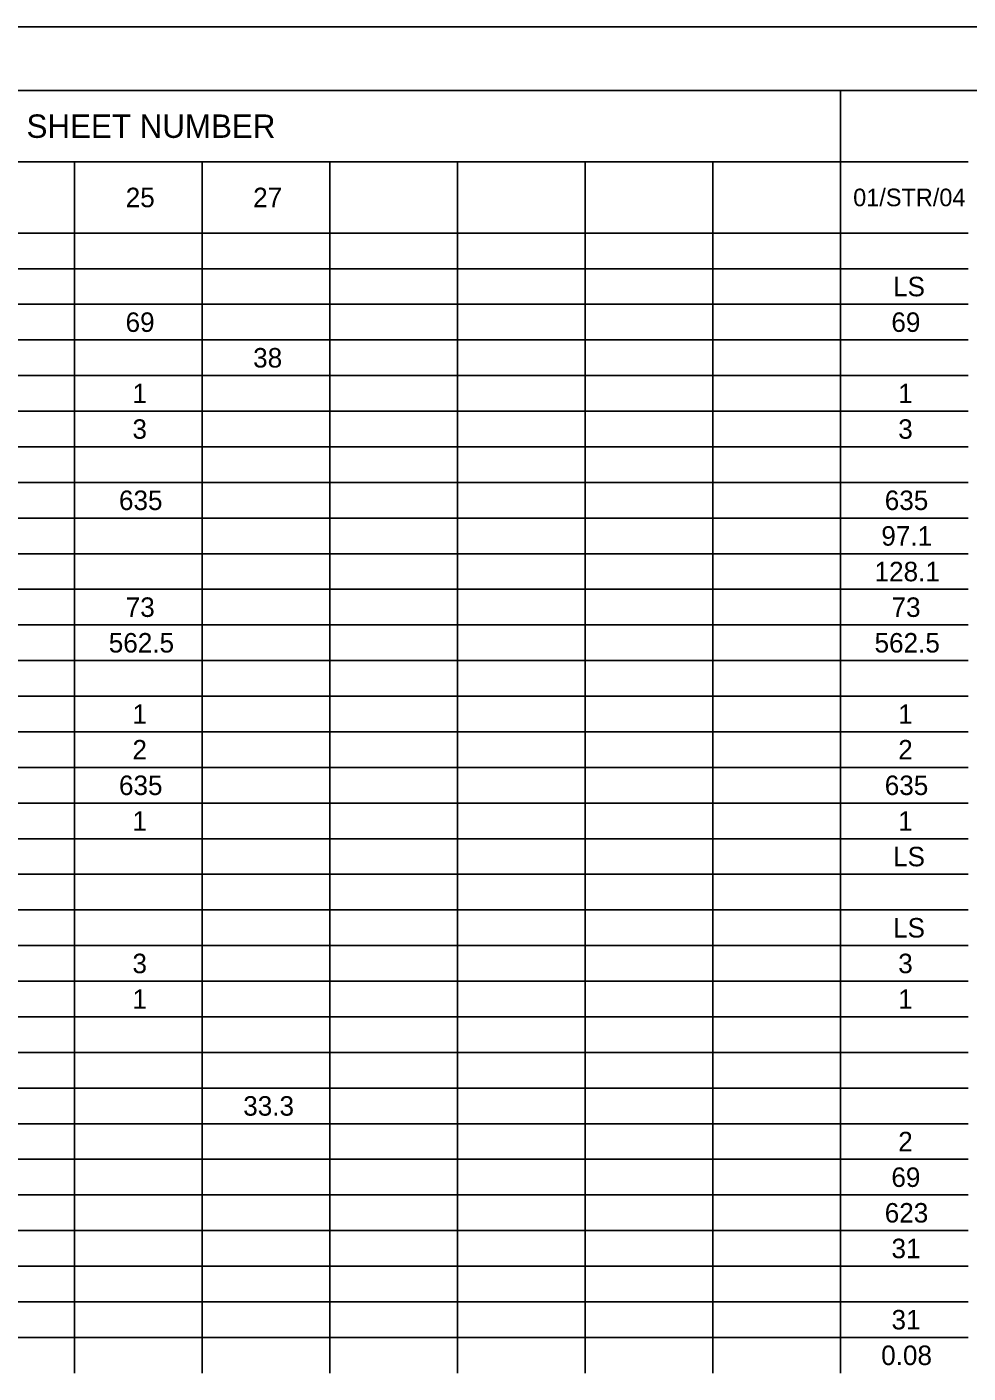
# Model space of a CAD drawing. Extents: x 0 to 34, y 0 to 22.
# Drawn here: x 6.14 to 13.53, y 11.42 to 22 of the extents above; entities that cross this region are included whole.
import ezdxf

# ---------------------------------------------------------------- set-up
doc = ezdxf.new("R2010")
doc.units = 0
for name, color, linetype in [('Default', 7, 'Continuous'), ('SH_Border', 7, 'Continuous'), ('SH_Cut_Line', 7, 'Continuous')]:
    doc.layers.add(name, color=color, linetype=linetype)

msp = doc.modelspace()

# ---------------------------------------------------------------- linework, layer by layer
at = {"layer": 'Default'}
for p, q in [((1.5, 21.5), (6.513, 21.5)), ((6.513, 21.5), (7.515, 21.5)), ((7.515, 21.5), (12.528, 21.5)), ((12.528, 21.5), (13.53, 21.5)), ((12.528, 21.5), (12.528, 21.22)), ((12.528, 21.22), (12.528, 20.94)), ((1.5, 20.94), (6.513, 20.94)), ((6.513, 20.94), (7.515, 20.94)), ((6.513, 20.94), (6.513, 20.66)), ((7.515, 20.94), (12.528, 20.94)), ((7.515, 20.94), (7.515, 20.66)), ((8.518, 20.94), (8.518, 20.66)), ((9.52, 20.94), (9.52, 20.66)), ((10.523, 20.94), (10.523, 20.66)), ((11.525, 20.94), (11.525, 20.66)), ((12.528, 20.94), (13.53, 20.94)), ((12.528, 20.94), (12.528, 20.66)), ((6.513, 20.66), (6.513, 20.38)), ((7.515, 20.66), (7.515, 20.38)), ((8.518, 20.66), (8.518, 20.38)), ((9.52, 20.66), (9.52, 20.38)), ((10.523, 20.66), (10.523, 20.38)), ((11.525, 20.66), (11.525, 20.38)), ((12.528, 20.66), (12.528, 20.38)), ((1.5, 20.38), (6.513, 20.38)), ((6.513, 20.38), (7.515, 20.38)), ((6.513, 20.38), (6.513, 20.1)), ((7.515, 20.38), (12.528, 20.38)), ((7.515, 20.38), (7.515, 20.1)), ((8.518, 20.38), (8.518, 20.1)), ((9.52, 20.38), (9.52, 20.1)), ((10.523, 20.38), (10.523, 20.1)), ((11.525, 20.38), (11.525, 20.1)), ((12.528, 20.38), (13.53, 20.38)), ((12.528, 20.38), (12.528, 20.1)), ((1.5, 20.1), (6.513, 20.1)), ((6.513, 20.1), (7.515, 20.1)), ((6.513, 20.1), (6.513, 18.7)), ((7.515, 20.1), (12.528, 20.1)), ((7.515, 20.1), (7.515, 18.7)), ((8.518, 20.1), (8.518, 18.7)), ((9.52, 20.1), (9.52, 18.7)), ((10.523, 20.1), (10.523, 18.7)), ((11.525, 20.1), (11.525, 18.7)), ((12.528, 20.1), (13.53, 20.1)), ((12.528, 20.1), (12.528, 18.7)), ((1.5, 19.82), (6.513, 19.82)), ((6.513, 19.82), (7.515, 19.82)), ((7.515, 19.82), (12.528, 19.82)), ((12.528, 19.82), (13.53, 19.82)), ((1.5, 19.54), (6.513, 19.54)), ((6.513, 19.54), (7.515, 19.54)), ((7.515, 19.54), (12.528, 19.54)), ((12.528, 19.54), (13.53, 19.54)), ((1.5, 19.26), (6.513, 19.26)), ((6.513, 19.26), (7.515, 19.26)), ((7.515, 19.26), (12.528, 19.26)), ((12.528, 19.26), (13.53, 19.26)), ((1.5, 18.98), (6.513, 18.98)), ((6.513, 18.98), (7.515, 18.98)), ((7.515, 18.98), (12.528, 18.98)), ((12.528, 18.98), (13.53, 18.98)), ((1.5, 18.7), (6.513, 18.7)), ((6.513, 18.7), (7.515, 18.7)), ((6.513, 18.7), (6.513, 18.14)), ((7.515, 18.7), (12.528, 18.7)), ((7.515, 18.7), (7.515, 18.14)), ((8.518, 18.7), (8.518, 18.14)), ((9.52, 18.7), (9.52, 18.14)), ((10.523, 18.7), (10.523, 18.14)), ((11.525, 18.7), (11.525, 18.14)), ((12.528, 18.7), (13.53, 18.7)), ((12.528, 18.7), (12.528, 18.14)), ((1.5, 18.42), (6.513, 18.42)), ((6.513, 18.42), (7.515, 18.42)), ((7.515, 18.42), (12.528, 18.42)), ((12.528, 18.42), (13.53, 18.42)), ((1.5, 18.14), (6.513, 18.14)), ((6.513, 18.14), (7.515, 18.14)), ((6.513, 18.14), (6.513, 17.86)), ((7.515, 18.14), (12.528, 18.14)), ((7.515, 18.14), (7.515, 17.86)), ((8.518, 18.14), (8.518, 17.86)), ((9.52, 18.14), (9.52, 17.86)), ((10.523, 18.14), (10.523, 17.86)), ((11.525, 18.14), (11.525, 17.86)), ((12.528, 18.14), (13.53, 18.14)), ((12.528, 18.14), (12.528, 17.86)), ((1.5, 17.86), (6.513, 17.86)), ((6.513, 17.86), (7.515, 17.86)), ((6.513, 17.86), (6.513, 17.58)), ((7.515, 17.86), (12.528, 17.86)), ((7.515, 17.86), (7.515, 17.58)), ((8.518, 17.86), (8.518, 17.58)), ((9.52, 17.86), (9.52, 17.58)), ((10.523, 17.86), (10.523, 17.58)), ((11.525, 17.86), (11.525, 17.58)), ((12.528, 17.86), (13.53, 17.86)), ((12.528, 17.86), (12.528, 17.58)), ((1.5, 17.58), (6.513, 17.58)), ((6.513, 17.58), (7.515, 17.58)), ((6.513, 17.58), (6.513, 17.3)), ((7.515, 17.58), (12.528, 17.58)), ((7.515, 17.58), (7.515, 17.3)), ((8.518, 17.58), (8.518, 17.3)), ((9.52, 17.58), (9.52, 17.3)), ((10.523, 17.58), (10.523, 17.3)), ((11.525, 17.58), (11.525, 17.3)), ((12.528, 17.58), (13.53, 17.58)), ((12.528, 17.58), (12.528, 17.3)), ((1.5, 17.3), (6.513, 17.3)), ((6.513, 17.3), (7.515, 17.3)), ((6.513, 17.3), (6.513, 17.02)), ((7.515, 17.3), (12.528, 17.3)), ((7.515, 17.3), (7.515, 17.02)), ((8.518, 17.3), (8.518, 17.02)), ((9.52, 17.3), (9.52, 17.02)), ((10.523, 17.3), (10.523, 17.02)), ((11.525, 17.3), (11.525, 17.02)), ((12.528, 17.3), (13.53, 17.3)), ((12.528, 17.3), (12.528, 17.02)), ((1.5, 17.02), (6.513, 17.02)), ((6.513, 17.02), (7.515, 17.02)), ((6.513, 17.02), (6.513, 16.74)), ((7.515, 17.02), (12.528, 17.02)), ((7.515, 17.02), (7.515, 16.74)), ((8.518, 17.02), (8.518, 16.74)), ((9.52, 17.02), (9.52, 16.74)), ((10.523, 17.02), (10.523, 16.74)), ((11.525, 17.02), (11.525, 16.74)), ((12.528, 17.02), (13.53, 17.02)), ((12.528, 17.02), (12.528, 16.74)), ((1.5, 16.74), (6.513, 16.74)), ((6.513, 16.74), (7.515, 16.74)), ((6.513, 16.74), (6.513, 16.18)), ((7.515, 16.74), (12.528, 16.74)), ((7.515, 16.74), (7.515, 16.18)), ((8.518, 16.74), (8.518, 16.18)), ((9.52, 16.74), (9.52, 16.18)), ((10.523, 16.74), (10.523, 16.18)), ((11.525, 16.74), (11.525, 16.18)), ((12.528, 16.74), (13.53, 16.74)), ((12.528, 16.74), (12.528, 16.18)), ((1.5, 16.46), (6.513, 16.46)), ((6.513, 16.46), (7.515, 16.46)), ((7.515, 16.46), (12.528, 16.46)), ((12.528, 16.46), (13.53, 16.46)), ((1.5, 16.18), (6.513, 16.18)), ((6.513, 16.18), (7.515, 16.18)), ((6.513, 16.18), (6.513, 15.9)), ((7.515, 16.18), (12.528, 16.18)), ((7.515, 16.18), (7.515, 15.9)), ((8.518, 16.18), (8.518, 15.9)), ((9.52, 16.18), (9.52, 15.9)), ((10.523, 16.18), (10.523, 15.9)), ((11.525, 16.18), (11.525, 15.9)), ((12.528, 16.18), (13.53, 16.18)), ((12.528, 16.18), (12.528, 15.9)), ((1.5, 15.9), (6.513, 15.9)), ((6.513, 15.9), (7.515, 15.9)), ((6.513, 15.9), (6.513, 15.62)), ((7.515, 15.9), (12.528, 15.9)), ((7.515, 15.9), (7.515, 15.62)), ((8.518, 15.9), (8.518, 15.62)), ((9.52, 15.9), (9.52, 15.62)), ((10.523, 15.9), (10.523, 15.62)), ((11.525, 15.9), (11.525, 15.62)), ((12.528, 15.9), (13.53, 15.9)), ((12.528, 15.9), (12.528, 15.62)), ((1.5, 15.62), (6.513, 15.62)), ((6.513, 15.62), (7.515, 15.62)), ((6.513, 15.62), (6.513, 15.34)), ((7.515, 15.62), (12.528, 15.62)), ((7.515, 15.62), (7.515, 15.34)), ((8.518, 15.62), (8.518, 15.34)), ((9.52, 15.62), (9.52, 15.34)), ((10.523, 15.62), (10.523, 15.34)), ((11.525, 15.62), (11.525, 15.34)), ((12.528, 15.62), (13.53, 15.62)), ((12.528, 15.62), (12.528, 15.34)), ((1.5, 15.34), (6.513, 15.34)), ((6.513, 15.34), (7.515, 15.34)), ((6.513, 15.34), (6.513, 14.78)), ((7.515, 15.34), (12.528, 15.34)), ((7.515, 15.34), (7.515, 14.78)), ((8.518, 15.34), (8.518, 14.78)), ((9.52, 15.34), (9.52, 14.78)), ((10.523, 15.34), (10.523, 14.78)), ((11.525, 15.34), (11.525, 14.78)), ((12.528, 15.34), (13.53, 15.34)), ((12.528, 15.34), (12.528, 14.78)), ((1.5, 15.06), (6.513, 15.06)), ((6.513, 15.06), (7.515, 15.06)), ((7.515, 15.06), (12.528, 15.06)), ((12.528, 15.06), (13.53, 15.06)), ((1.5, 14.78), (6.513, 14.78)), ((6.513, 14.78), (7.515, 14.78)), ((6.513, 14.78), (6.513, 14.5)), ((7.515, 14.78), (12.528, 14.78)), ((7.515, 14.78), (7.515, 14.5)), ((8.518, 14.78), (8.518, 14.5)), ((9.52, 14.78), (9.52, 14.5)), ((10.523, 14.78), (10.523, 14.5)), ((11.525, 14.78), (11.525, 14.5)), ((12.528, 14.78), (13.53, 14.78)), ((12.528, 14.78), (12.528, 14.5)), ((1.5, 14.5), (6.513, 14.5)), ((6.513, 14.5), (7.515, 14.5)), ((6.513, 14.5), (6.513, 14.22)), ((7.515, 14.5), (12.528, 14.5)), ((7.515, 14.5), (7.515, 14.22)), ((8.518, 14.5), (8.518, 14.22)), ((9.52, 14.5), (9.52, 14.22)), ((10.523, 14.5), (10.523, 14.22)), ((11.525, 14.5), (11.525, 14.22)), ((12.528, 14.5), (13.53, 14.5)), ((12.528, 14.5), (12.528, 14.22)), ((1.5, 14.22), (6.513, 14.22)), ((6.513, 14.22), (7.515, 14.22)), ((6.513, 14.22), (6.513, 13.94)), ((7.515, 14.22), (12.528, 14.22)), ((7.515, 14.22), (7.515, 13.94)), ((8.518, 14.22), (8.518, 13.94)), ((9.52, 14.22), (9.52, 13.94)), ((10.523, 14.22), (10.523, 13.94)), ((11.525, 14.22), (11.525, 13.94)), ((12.528, 14.22), (13.53, 14.22)), ((12.528, 14.22), (12.528, 13.94)), ((1.5, 13.94), (6.513, 13.94)), ((6.513, 13.94), (7.515, 13.94)), ((6.513, 13.94), (6.513, 11.7)), ((7.515, 13.94), (12.528, 13.94)), ((7.515, 13.94), (7.515, 11.7)), ((8.518, 13.94), (8.518, 11.7)), ((9.52, 13.94), (9.52, 11.7)), ((10.523, 13.94), (10.523, 11.7)), ((11.525, 13.94), (11.525, 11.7)), ((12.528, 13.94), (13.53, 13.94)), ((12.528, 13.94), (12.528, 11.7)), ((1.5, 13.66), (6.513, 13.66)), ((6.513, 13.66), (7.515, 13.66)), ((7.515, 13.66), (12.528, 13.66)), ((12.528, 13.66), (13.53, 13.66)), ((1.5, 13.38), (6.513, 13.38)), ((6.513, 13.38), (7.515, 13.38)), ((7.515, 13.38), (12.528, 13.38)), ((12.528, 13.38), (13.53, 13.38)), ((1.5, 13.1), (6.513, 13.1)), ((6.513, 13.1), (7.515, 13.1)), ((7.515, 13.1), (12.528, 13.1)), ((12.528, 13.1), (13.53, 13.1)), ((1.5, 12.82), (6.513, 12.82)), ((6.513, 12.82), (7.515, 12.82)), ((7.515, 12.82), (12.528, 12.82)), ((12.528, 12.82), (13.53, 12.82)), ((1.5, 12.54), (6.513, 12.54)), ((6.513, 12.54), (7.515, 12.54)), ((7.515, 12.54), (12.528, 12.54)), ((12.528, 12.54), (13.53, 12.54)), ((1.5, 12.26), (6.513, 12.26)), ((6.513, 12.26), (7.515, 12.26)), ((7.515, 12.26), (12.528, 12.26)), ((12.528, 12.26), (13.53, 12.26)), ((1.5, 11.98), (6.513, 11.98)), ((6.513, 11.98), (7.515, 11.98)), ((7.515, 11.98), (12.528, 11.98)), ((12.528, 11.98), (13.53, 11.98)), ((1.5, 11.7), (6.513, 11.7)), ((6.513, 11.7), (7.515, 11.7)), ((6.513, 11.7), (6.513, 11.42)), ((7.515, 11.7), (12.528, 11.7)), ((7.515, 11.7), (7.515, 11.42)), ((8.518, 11.7), (8.518, 11.42)), ((9.52, 11.7), (9.52, 11.42)), ((10.523, 11.7), (10.523, 11.42)), ((11.525, 11.7), (11.525, 11.42)), ((12.528, 11.7), (13.53, 11.7)), ((12.528, 11.7), (12.528, 11.42))]:
    msp.add_line(p, q, dxfattribs=at)
at = {"layer": 'SH_Border'}
msp.add_lwpolyline([(1.5, 21.5), (33.5, 21.5), (33.5, 0.5), (1.5, 0.5)], close=True, dxfattribs=at)
at = {"layer": 'SH_Cut_Line'}
msp.add_lwpolyline([(0, 0), (34, 0), (34, 22), (0, 22)], close=True, dxfattribs=at)

# ---------------------------------------------------------------- texts
at = {"layer": 'Default'}
for s, height, p in [('SHEET NUMBER', 0.184, (6.135, 21.128)), ('25', 0.1533, (6.914, 20.583)), ('27', 0.1533, (7.915, 20.583)), ('01/STR/04', 0.138, (12.628, 20.591)), ('LS', 0.1533, (12.941, 19.883)), ('69', 0.1533, (6.913, 19.603)), ('69', 0.1533, (12.928, 19.603)), ('38', 0.1533, (7.915, 19.323)), ('1', 0.153, (6.967, 19.043)), ('1', 0.153, (12.982, 19.043)), ('3', 0.153, (6.967, 18.763)), ('3', 0.153, (12.982, 18.763)), ('635', 0.1533, (6.861, 18.203)), ('635', 0.1533, (12.876, 18.203)), ('97.1', 0.1533, (12.849, 17.923)), ('128.1', 0.1533, (12.796, 17.643)), ('73', 0.1533, (6.914, 17.363)), ('73', 0.1533, (12.929, 17.363)), ('562.5', 0.1533, (6.781, 17.083)), ('562.5', 0.1533, (12.796, 17.083)), ('1', 0.153, (6.967, 16.523)), ('1', 0.153, (12.982, 16.523)), ('2', 0.153, (6.967, 16.243)), ('2', 0.153, (12.982, 16.243)), ('635', 0.1533, (6.861, 15.963)), ('635', 0.1533, (12.876, 15.963)), ('1', 0.153, (6.967, 15.683)), ('1', 0.153, (12.982, 15.683)), ('LS', 0.1533, (12.941, 15.403)), ('LS', 0.1533, (12.941, 14.843)), ('3', 0.153, (6.967, 14.563)), ('3', 0.153, (12.982, 14.563)), ('1', 0.153, (6.967, 14.283)), ('1', 0.153, (12.982, 14.283)), ('33.3', 0.1533, (7.837, 13.443)), ('2', 0.153, (12.982, 13.163)), ('69', 0.1533, (12.928, 12.883)), ('623', 0.1533, (12.876, 12.603)), ('31', 0.1533, (12.929, 12.323)), ('31', 0.1533, (12.929, 11.763)), ('0.08', 0.1533, (12.848, 11.483))]:
    msp.add_text(s, height=height, dxfattribs=at).set_placement(p)

doc.saveas('drawing.dxf')
